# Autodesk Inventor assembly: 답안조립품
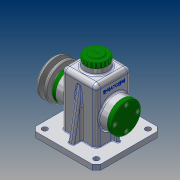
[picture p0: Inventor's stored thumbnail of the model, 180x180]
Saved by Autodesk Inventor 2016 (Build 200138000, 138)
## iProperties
Created: 2018-10
Part Number: 답안조립품
Material: 일반
Document SubType Name: Assembly
Designer: user
Author: user
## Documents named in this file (14)
- C:\Users\user\Desktop\481016V1002\답안조립품.iam
- C:\Users\user\Desktop\481016V1002\본체.ipt
- C:\Users\user\Desktop\481016V1002\베어링 15 x 35 x 11.ipt
- C:\Users\user\Desktop\481016V1002\축.ipt
- C:\Users\user\Desktop\481016V1002\멈춤링 15 x 1.ipt
- C:\Users\user\Desktop\481016V1002\앞커버.ipt
- C:\Users\user\Desktop\481016V1002\뒤커버.ipt
- C:\Users\user\Desktop\481016V1002\볼트 M4 x 10.ipt
- C:\Users\user\Desktop\481016V1002\상부캡.ipt
- C:\Users\user\Desktop\481016V1002\키 5 x 5 x 14.ipt
- C:\Users\user\Desktop\481016V1002\V-벨트풀리.ipt
- C:\Users\user\Desktop\481016V1002\와셔.ipt
- C:\Users\user\Desktop\481016V1002\볼트 M6 x 12.ipt
- C:\Users\user\Desktop\481016V1002\오일실 15 25 7.ipt
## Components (1 placed, 1 different names)
1. V-벨트풀리:1
